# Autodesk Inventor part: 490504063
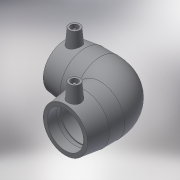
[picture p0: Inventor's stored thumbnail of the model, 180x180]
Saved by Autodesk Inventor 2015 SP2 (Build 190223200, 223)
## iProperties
Created: 2017-06
Part Number: 490504063
Material: Generic
Description: PLASSON 90° ELBOW 63
Document SubType Name: Modeling
Designer: KIM
Mass: 55.0731 g
Surface Area: 148.067 cm^2
Volume: 55.0731 cm^3
Density: 1 g/cm^3
Appearance: Default
Author: KIM
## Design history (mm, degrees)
derived "490504.ipt"
feature "Solid1::490504.ipt"
tag "TaggingFeature1"
body "Solid1"
other parameters: "d2" = 81, "d4" = 32.75, "d5" = 72.9, "d8" = 168 deg, "d10" = 22.8, "d11" = 7.6, "d14" = 17.6296, "d18" = 63, "d19" = 3.52592, "d20" = 168 deg, "d22" = 74.52, "d23" = 81, "d24" = 72.2844, "d29" = 59, "d30" = 15, "d31" = 78.6, "d34" = 5 deg, "d35" = 15, "d39" = 5 deg, "d41" = 4, "d42" = 14, "d43" = 0, "d45" = 4, "d46" = 14, "d47" = 0, "d49" = 63, "d50" = 53.55, "d51" = 22.8, "d52" = 57, "d54" = 90 deg, "d65" = 63, "d67" = 45 deg, "d71" = 90 deg, "d75" = 4.05, "d82" = 45 deg, "d83" = 57, "d84" = 72.9, "d86" = 36.45, "d87" = 90 deg, "d90" = 57, "d91" = 0, "d92" = 57, "d93" = 0, "d94" = 90 deg, "d95" = 37.26, "d98" = 131, "d101" = 3, "d102" = 0, "d103" = 3, "d104" = 0, "d105" = 16.53, "d106" = 4.1325, "d107" = 131, "d110" = 31.35, "d_" = 63, "L_" = 131, "L_1" = 57, "D_" = 81, "A_" = 59, "d_2" = 12
